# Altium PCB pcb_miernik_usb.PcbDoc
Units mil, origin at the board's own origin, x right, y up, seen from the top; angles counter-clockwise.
Board outline 6000 x 4000 mil, 2 copper layers (Top Layer, Bottom Layer); 39 components, 50 nets, 152 pads, 21 vias.
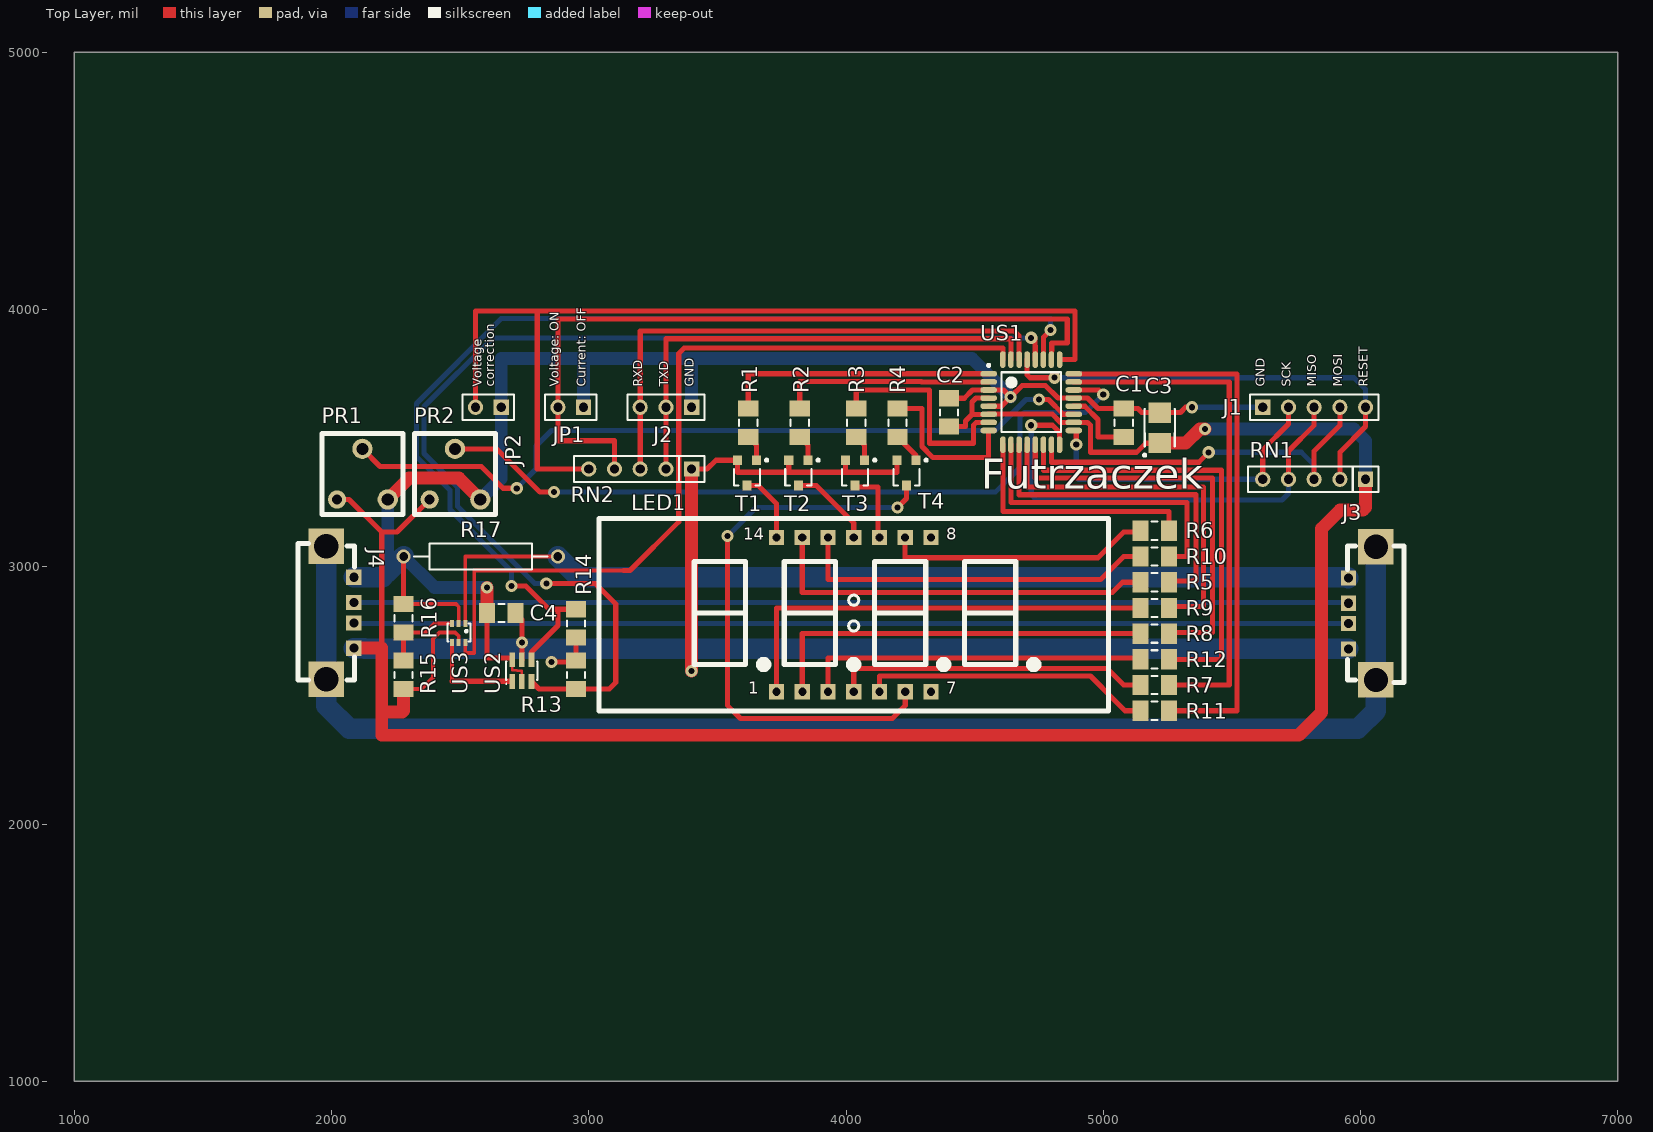
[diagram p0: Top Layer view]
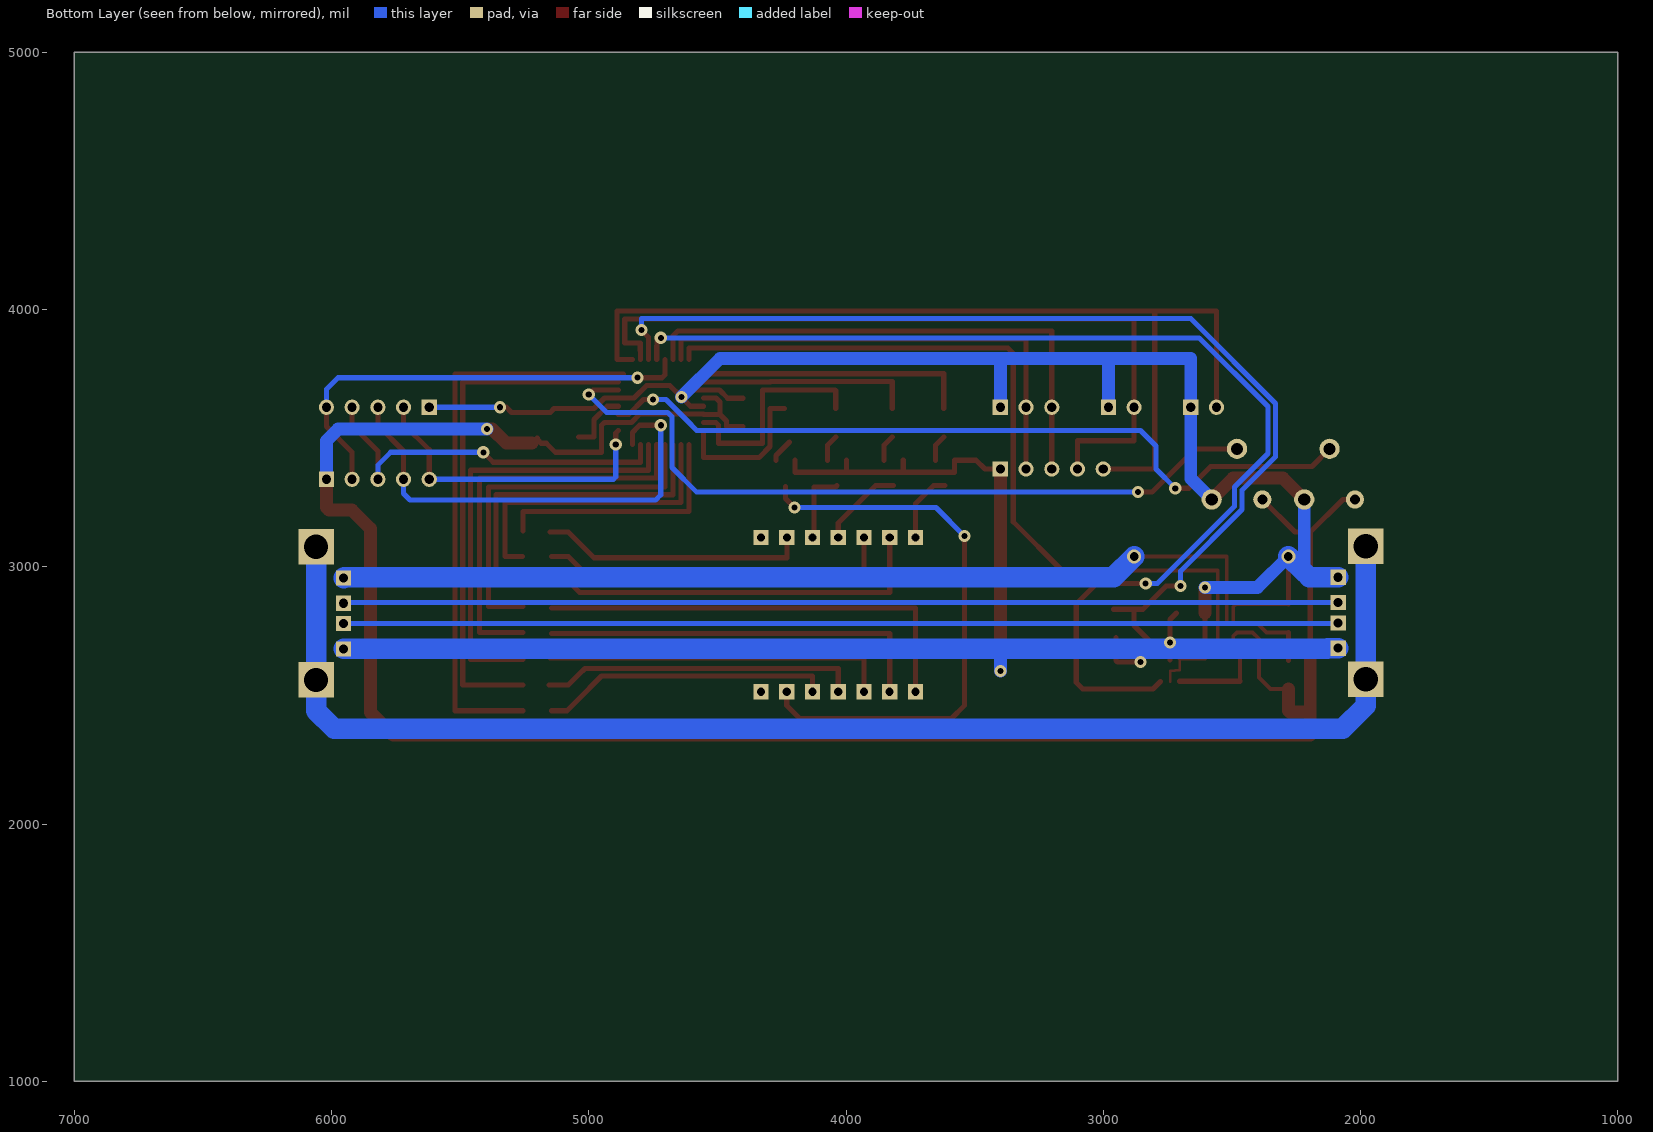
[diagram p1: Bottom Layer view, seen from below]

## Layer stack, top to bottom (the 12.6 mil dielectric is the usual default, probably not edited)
Top Layer: signal copper 1.4
Dielectric: dielectric 12.6, FR-4, Dk 4.8
Bottom Layer: signal copper 1.4

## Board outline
1000,1000 7000,1000 7000,5000 1000,5000

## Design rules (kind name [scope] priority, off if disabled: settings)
Clearance [All] p1: gap=10
PolygonConnect [All] p1: connectstyle=Relief reliefconductorwidth=10 reliefentries=4 polygonreliefangle="90 Angle"
RoutingVias [All] p1: holewidth=28 width=50 viastyle="Through Hole" minholewidth=28 minwidth=50 maxholewidth=28 maxwidth=50
SilkscreenOverComponentPads [All] p1: minsilkscreentomaskgap=10
SolderMaskExpansion [All] p1: expansion=4
Width [All] p1: maxlimit=100 minlimit=10 preferedwidth=50
27 further rules are at their usual default settings.

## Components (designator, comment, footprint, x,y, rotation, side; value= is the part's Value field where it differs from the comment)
C1 "100n" MELF-1206 5080,3560 r270 top
C2 "100n" MELF-1206 4400,3600 r270 top
C3 "22u/16V B" "Tantal B 3528-1411" 5220,3540 r90 top
C4 "100n" MELF-1206 2660,2820 r0 top
J1 "Header 5" HDR1X5 5620,3620 r0 top
J2 "Header 3" HDR1X3 3400,3620 r180 top
J3 "USB connector female" "USB A ¿eñski" 6060,2560 r90 top
J4 "USB connector male" "USB A mêski" 1980,3080 r270 top
JP1 "Header 2" HDR1X2 2980,3620 r180 top
JP2 "Header 2" HDR1X2 2660,3620 r180 top
LED1 "AF5643" "Wyœw LED-AF5643" 3040,2440 r0 top
PR1 "10k" "pot mont poziom" 2120,3360 r0 top
PR2 "10k" "pot mont poziom" 2480,3360 r0 top
R1 "4,7k" MELF-1206 3620,3560 r270 top
R2 "4,7k" MELF-1206 3820,3560 r270 top
R3 "4,7k" MELF-1206 4040,3560 r270 top
R4 "4,7k" MELF-1206 4200,3560 r270 top
R5 "100" MELF-1206 5200,2940 r180 top
R6 "100" MELF-1206 5200,3140 r180 top
R7 "100" MELF-1206 5200,2540 r180 top
R8 "100" MELF-1206 5200,2740 r180 top
R9 "100" MELF-1206 5200,2840 r180 top
R10 "100" MELF-1206 5200,3040 r180 top
R11 "100" MELF-1206 5200,2440 r180 top
R12 "100" MELF-1206 5200,2640 r180 top
R13 "4,7k" MELF-1206 2950,2580 r90 top
R14 "4,7k" MELF-1206 2950,2780 r270 top
R15 "56k" MELF-1206 2280,2580 r270 top
R16 "33k" MELF-1206 2280,2800 r270 top
R17 "0,1 1W" "rez 15mm" 2580,3040 r0 top
RN1 "4x10k" SIL5 6020,3340 r180 top
RN2 "4x10k" SIL5 3400,3380 r180 top
T1 "BC857" 318-08 3615,3365 r180 top
T2 "BC857" 318-08 3815,3365 r180 top
T3 "BC857" 318-08 4035,3365 r180 top
T4 "BC857" 318-08 4235,3365 r180 top
US1 "ATmega8" 32A_N 4720,3640 r0 top
US2 "MCP3425" SOT-23-6 2740,2596.22 r0 top
US3 "NC7SB3157" SC70 2520,2780 r180 top

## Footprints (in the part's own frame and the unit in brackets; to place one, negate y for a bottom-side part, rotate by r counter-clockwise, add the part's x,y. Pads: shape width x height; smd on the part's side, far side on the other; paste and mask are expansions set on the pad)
32A_N [mm] "Thin QFP, 32-Leads, Body 7x7mm, Pitch 0.8mm, IPC Medium Density"
  oval 1.65x0.55 smd: 1(-4.2,2.8) 2(-4.2,2) 3(-4.2,1.2) 4(-4.2,0.4) 5(-4.2,-0.4) 6(-4.2,-1.2) 7(-4.2,-2) 8(-4.2,-2.8) 17(4.2,-2.8) 18(4.2,-2) 19(4.2,-1.2) 20(4.2,-0.4) 21(4.2,0.4) 22(4.2,1.2) 23(4.2,2) 24(4.2,2.8)
  oval 0.55x1.65 smd: 9(-2.8,-4.2) 10(-2,-4.2) 11(-1.2,-4.2) 12(-0.4,-4.2) 13(0.4,-4.2) 14(1.2,-4.2) 15(2,-4.2) 16(2.8,-4.2) 25(2.8,4.2) 26(2,4.2) 27(1.2,4.2) 28(0.4,4.2) 29(-0.4,4.2) 30(-1.2,4.2) 31(-2,4.2) 32(-2.8,4.2)
  silkscreen extent -4.32,-2.95 2.95,3.75, body extent -3.5,-3.5 3.5,3.5, height 1.2
318-08 [mm] "SOT-23; 3 Leads; Body 3.0 x 2.6 mm, inc. leads (LxW max)"
  rect 0.9x0.95 smd: 1(-0.95,-1.25) 2(0.95,-1.25) 3(0,1.25)
  silkscreen extent -2.08,-1.37 1.3,1.25
HDR1X2 [mm] "Connector; Header; 2 Position"
  rect 1.5x1.5 hole 0.9: 1(0,0)
  round 1.5 hole 0.9: 2(2.54,0)
  silkscreen extent -1.27,-1.27 3.81,1.27
HDR1X3 [mm] "Connector; Header; 3 Position"
  rect 1.5x1.5 hole 0.9: 1(0,0)
  round 1.5 hole 0.9: 2(2.54,0) 3(5.08,0)
  silkscreen extent -1.27,-1.27 6.35,1.27
HDR1X5 [mm] "Connector; Header; 5 Position"
  rect 1.5x1.5 hole 0.9: 1(0,0)
  round 1.5 hole 0.9: 2(2.54,0) 3(5.08,0) 4(7.62,0) 5(10.16,0)
  silkscreen extent -1.27,-1.27 11.43,1.27
MELF-1206 [mm] "Metal Electrode Face (MELF) Resistor; Body 3.2 x 1.8 mm (LxDia)"
  rect 1.6x2 smd: 1(-1.4,0) 2(1.4,0)
  silkscreen extent -0.3,-0.9 0.3,0.9, body extent -2.3,-1.1 2.3,1.1, height 1.85
"pot mont poziom" [mm]
  round 1.8 hole 1: a(-2.5,-2.5)
  round 2 hole 1.2: b(2.5,-2.5) c(0,2.5)
  silkscreen extent -4,-4 4,4
"rez 15mm" [mm]
  round 1.4 hole 0.85: 1(-7.62,0) 2(7.62,0)
  silkscreen extent -6.6,-1.27 6.6,1.27, body extent -5.08,-1.27 5.08,1.27, height 2.54
SC70 [mm]
  rect 0.4x0.7 smd: 1(0,0) 2(0.65,0) 3(1.3,0) 4(1.3,1.9) 5(0.65,1.9) 6(0,1.9)
  silkscreen extent -0.51,0 1.78,1.78, body extent -0.51,0 1.78,1.78, height 1
SIL5 [mm] "Connector; Header; 9 Position"
  rect 1.5x1.5 hole 0.9: 1(0,0)
  round 1.5 hole 0.9: 2(2.54,0) 3(5.08,0) 4(7.62,0) 5(10.16,0)
  silkscreen extent -1.27,-1.27 11.6,1.27
SOT-23-6 [mm]
  rect 0.55x1.45 smd: 1(-0.95,-1.075) 2(0,-1.075) 3(0.95,-1.075) 4(0.95,1.075) 5(0,1.075) 6(-0.95,1.075)
  silkscreen extent -1.57,-1.35 1.55,0.9, body extent -1.52,-1.02 1.52,1.02, height 1.45
"Tantal B 3528-1411" [mm] "Capacitor, SM Tantalum; Body 3.5 x 2.8 mm (LxW typ)"
  rect 2x2.2 smd: 1(-1.5,0) 2(1.5,0)
  silkscreen extent -2.82,-1.5 1.85,1.62, body extent -2.6,-1.2 2.6,1.2, height 2.5
"USB A mêski" [mm] "z³¹cze USB typu A na krawêdzi p³ytki"
  rect 1.5x1.5 hole 0.9: 1(10.07,2.71) 2(7.57,2.71) 3(5.57,2.71) 4(3.07,2.71)
  rect 3.5x3.5 hole 2.4: 5(0,0) 5(13.14,0)
  silkscreen extent -0.25,-2.79 13.21,2.79
"USB A ¿eñski" [mm] "z³¹cze USB typu A na krawêdzi p³ytki"
  rect 1.5x1.5 hole 0.9: 1(3.07,2.71) 2(5.57,2.71) 3(7.57,2.71) 4(10.07,2.71)
  rect 3.5x3.5 hole 2.4: 5(0,0) 5(13.14,0)
  silkscreen extent -0.25,-2.79 13.21,2.79
"Wyœw LED-AF5643" [mm]
  rect 1.5x1.5 hole 0.8: 1(17.53,1.88) 2(20.07,1.88) 3(22.61,1.88) 4(25.15,1.88) 5(27.69,1.88) 6(30.23,1.88) 7(32.77,1.88) 8(32.766,17.12) 9(30.226,17.12) 10(27.686,17.12) 11(25.146,17.12) 12(22.606,17.12) 13(20.066,17.12) 14(17.526,17.12)
  silkscreen extent 0,0 50.3,19, body extent 0,0 50.3,19, height 8

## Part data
C1 C2 C4: library part kondensator
C3: library part "kond biegunowy", "Polarized Capacitor"
J1: "Header, 5-Pin"
J2: "Header, 3-Pin"
J3 J4: library part "USB connector"
JP1 JP2: "Header, 2-Pin"
LED1: library part "wyœwietlacz LED-AF5643"
PR1 PR2: library part "pot mont"
R1 R2 R3 R4 R5 R6 R7 R8 R9 R10 R11 R12 R13 R14 R15 R16 R17: library part rezystor
RN1 RN2: library part "drab rez x 4", "drab rez x 4"
T1 T2 T3 T4: library part BC857ALT1, "General Purpose Transistor PNP Silicon"
US1: library part ATmega8-16AC, "8-Bit AVR Microcontroller with 8K Bytes of In-System Programmable Flash Memory"
US2: "A/D 16-bit I2C"

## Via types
v1: diameter 47.24, hole 23.62, Top Layer to Bottom Layer, 21 vias

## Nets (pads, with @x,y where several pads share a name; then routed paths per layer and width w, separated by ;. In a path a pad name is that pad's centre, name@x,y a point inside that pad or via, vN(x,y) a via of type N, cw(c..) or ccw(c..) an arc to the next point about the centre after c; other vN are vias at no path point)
+5V: C2.2 C3.1 C4.2 J3.1 J4.1 PR1.a PR2.a R13.2 R14.2 R15.2 RN1.1 RN2.1 T1.2 T2.2 T3.2 T4.2 US1.4 US1.6 US1.18 US2.5 US3.5 | length 15120.2
  Top Layer w15: R15.2 2349.88,2524.88 2395,2570 2395,2720 2420,2745 2480,2745 2494.41,2730.59 US3.5
  Top Layer w20: PR1.a 2068.43,3261.57 2195,3135 ; 2195,2524.88 2195,2683.54 2195,3135 ; PR2.a 2255,3135 2195,3135 ; C4.2 2740,2795.12 v1(2740,2705) US2.5 ; v1(2855,2630) 2944.88,2630 R13.2 R14.2 ; RN2.1 3460,3380 3494.21,3414.21 T1.2 3577.6,3367.4 4197.6,3367.4 T4.2 ; 3777.6,3369.8 T2.2 ; 3997.6,3369.8 T3.2 ; C2.2 4464.88,3544.88 4465,3545 4465,3567.01 4490,3592.01 ; US1.6@4553.98,3592.09 4520.22,3592.09 4520.14,3592.01 4490,3592.01 ; US1.6 4555.31,3593.43 4640.85,3593.43 4701.73,3593.43 4701.93,3593.62 4738.07,3593.62 4738.27,3593.43 4801.57,3593.43 4833.74,3561.26 US1.18 4938.74,3561.26 4950,3550 4950,3445 5130,3445 5165,3480 5185,3480 5195.94,3490.94 5210,3490.94 C3.1@5200,3500.94 ; US1.4 4505.75,3655.75 4490,3640 4490,3592.01
  Top Layer w50: J4.1 2195,2683.54 2195,2435 ; R15.2 2280,2440 2275,2435 2195,2435 ; v1(3400,2595) RN2.1 ; C3.1 5320.94,3480.94 5375,3535 v1(5395,3535) ; RN1.1 6020,3230 6010,3220 5920,3220 5849.13,3149.13 5849.13,2434.13 5760,2345 2195,2345 2195,2435
  Bottom Layer w20: 2740,2680.87 v1(2740,2705) ; v1(2855,2630) 2855,2675.87
  Bottom Layer w50: v1(3400,2595) 3400,2675.87 ; v1(5395,3535) 5975,3535 6020,3490 RN1.1
  Bottom Layer w80: J4.1 2126.69,2683.54 ; 2129.37,2680.87 2740,2680.87 J3.1
A: R5.1 US1.11 | length 1325.9
  Top Layer w20: US1.11 4672.76,3280 5360,3280 5360,2945 5265.12,2945 R5.1@5255.12,2935
A1: R1.1 US1.1 | length 1069.8
  Top Layer w20: R1.1 3620,3750.24 US1.1
A2: R2.1 US1.2 | length 840
  Top Layer w20: R2.1 3820,3720 4292.43,3720 4293.69,3718.74 US1.2
A3: R3.1 US1.7 | length 867.7
  Top Layer w20: R3.1 4040,3685 4042.48,3687.48 4325,3687.48 4325,3480 4495,3480 4495,3550 4506.26,3561.26 US1.7
A4: R4.1 US1.8 | length 584.6
  Top Layer w20: 4240,3615.12 4295,3615.12 4295,3467.57 4337.57,3425 4554.65,3425 US1.8
B: R6.1 US1.9 | length 980
  Top Layer w20: US1.9 4609.76,3215 5255.12,3215 R6.1
C: R7.1 US1.23 | length 2018.3
  Top Layer w20: US1.23 5490,3718.74 5490,2540 R7.1
D: R8.1 US1.13 | length 1588.8
  Top Layer w20: US1.13 4735.75,3345 5425,3345 5425,2745 R8.1@5255.12,2745
DP: R12.1 US1.14 | length 1732.3
  Top Layer w20: US1.14 4767.24,3375 5460,3375 5460,2640 R12.1
E: R9.1 US1.12 | length 1450.3
  Top Layer w20: US1.12 4704.25,3310 5390,3310 5390,2845 R9.1@5255.12,2845
F: R10.1 US1.10 | length 1186
  Top Layer w20: US1.10 4641.26,3250 5325,3250 5325,3040 R10.1@5257.36,3040
G: R11.1 US1.24 | length 2229.5
  Top Layer w20: US1.24@4865.35,3750 5520,3750 5520,2440 R11.1
GND: C1.1 C2.1 C3.2 C4.1 J1.1 J2.1 J4.4 JP1.1 JP2.1 PR1.b PR2.b R16.1 R17.1 US1.3 US1.5 US1.21 US2.2 US2.6 US3.2 | length 6669.5
  Top Layer w10: US2.6 2702.6,2597.44 2719.64,2597.44 2722.08,2595 2740,2595 US2.2
  Top Layer w15: R16.1 2483.7,2855.12 2494.41,2844.41 US3.2
  Top Layer w20: R16.1 R17.1 ; C4.1 2604.88,2730.12 2604.88,2645 US2.6@2702.6,2645 ; C2.1 4400.12,3655 4460,3655 4492.24,3687.24 US1.3 4612.76,3687.24 v1(4640,3660) ; US1.5 4604.25,3624.25 v1(4640,3660) ; v1(5345,3620) 5320,3620 5300,3600 5150,3600 5135,3615 4980,3615 4939.25,3655.75 US1.21 4824.25,3655.75 4775,3705 4685,3705 v1(4640,3660)
  Top Layer w50: PR1.b 2301.85,3345 2495,3345 PR2.b ; C4.1@2605,2820.12 v1(2605,2920)
  Bottom Layer w20: v1(5345,3620) J1.1
  Bottom Layer w50: 2218.43,2978.43 PR1.b ; R17.1 2400,2920 v1(2605,2920) ; PR2.b 2660,3343.15 JP2.1 2660,3810 2980,3810 ; JP1.1 2980,3810 ; J2.1 3400,3805 3395,3810 ; v1(4640,3660) 4490,3810 3395,3810 ; 2980,3810 3395,3810
  Bottom Layer w80: J4.4 2199.13,2959.13 ; 2218.43,2978.43 R17.1
JP1: JP1.2 RN2.4 US1.26 | length 3002.6
  Top Layer w20: RN2.4 3100,3490 2880,3490 JP1.2 2880,3963.74 4860,3963.74 4860,3870 4800,3870 4800,3840.37 4799.41,3839.78 4799.41,3806.02 US1.26
JP2: JP2.2 RN2.5 US1.25 | length 3765.6
  Top Layer w20: JP2.2 2560,3993.74 2800,3993.74 ; RN2.5 2800,3380 2800,3993.74 ; US1.25 4890,3805.35 4890,3993.74 2800,3993.74
MISO: J1.3 RN1.4 US1.16 | length 1834.4
  Top Layer w20: v1(4720,3550) 4802.57,3550 4807.57,3545 4830.24,3522.34 US1.16 ; RN1.4 5720,3450 5820,3550 J1.3
  Bottom Layer w20: v1(4720,3550) 4720,3280 4740,3260 5695,3260 5720,3285 RN1.4
MOSI: J1.4 RN1.3 US1.15 | length 1502.8
  Top Layer w20: US1.15 4798.74,3406.26 5371.26,3406.26 v1(5410,3445) ; RN1.3 5820,3450 5920,3550 J1.4
  Bottom Layer w20: v1(5410,3445) 5770,3445 5820,3395 RN1.3
NetC1_2: C1.2 US1.20 | length 243.5
  Top Layer w20: US1.20 4928.32,3624.25 4980,3572.57 4980,3505 5039.88,3505
NetJ3_2: J3.2 J4.2 | length 3863.9
  Bottom Layer w20: J4.2@2089.37,2779.29 J3.2
NetJ3_3: J3.3 J4.3 | length 3863.9
  Bottom Layer w20: J4.3 J3.3@5950.63,2860.71
NetJ3_4: J3.4 R17.2 US3.1 | length 3727.9
  Top Layer w15: US3.1 2520,3040 R17.2
  Bottom Layer w80: R17.2 2960,2960 5949.76,2960 J3.4
NetJ3_5: J3.5 J4.5 | length 5403.6
  Bottom Layer w80: J4.5@1980,3080 1980,2562.68 1980,2460 2070,2370 5990,2370 6060,2440 6060,2560 J3.5@6060,3077.32
NetLED1_1: LED1.1 R9.2 | length 1740.7
  Top Layer w20: LED1.1 3730.16,2840 5000,2840 5090,2840 R9.2
NetLED1_2: LED1.2 R8.2 | length 1540.7
  Top Layer w20: LED1.2 3830.16,2740 5080,2740 R8.2
NetLED1_3: LED1.3 R12.2 | length 1350.8
  Top Layer w20: LED1.3 3930.16,2645 5060,2645 R12.2@5150,2645
NetLED1_4: LED1.4 R7.2 | length 1242.8
  Top Layer w20: LED1.4 4030.16,2605 5015,2605 5040,2580 5080,2540 R7.2@5155,2540
NetLED1_5: LED1.5 R11.2 | length 1131.6
  Top Layer w20: LED1.5 4130.16,2575 4950,2575 5045,2480 5085,2440 R11.2
NetLED1_6: LED1.6 T4.3 | length 2246.4
  Top Layer w20: v1(3540,3120) 3540,2460 3590,2410 4180,2410 4230.16,2460.16 LED1.6 ; v1(4200,3230) 4235,3265 T4.3@4235,3310.79
  Bottom Layer w20: v1(3540,3120) 3650,3230 v1(4200,3230)
NetLED1_9: LED1.9 R6.2 | length 1040.4
  Top Layer w20: LED1.9 4230,3035 4980,3035 5080,3135 R6.2@5150,3135
NetLED1_10: LED1.10 T3.3 | length 283.4
  Top Layer w20: T3.3 4040.79,3310 4125,3310 LED1.10@4125,3119.02
NetLED1_11: LED1.11 T2.3 | length 331.4
  Top Layer w20: T2.3 3884.21,3315.79 4030,3170 LED1.11
NetLED1_12: LED1.12 R10.2 | length 1416.2
  Top Layer w20: LED1.12 3930,2950 4990,2950 5080,3040 R10.2
NetLED1_13: LED1.13 R5.2 | length 1545.5
  Top Layer w20: LED1.13 3830,2900 5000,2900 5035,2900 5075,2940 R5.2
NetLED1_14: LED1.14 T1.3 | length 275.3
  Top Layer w20: T1.3 3659.21,3315.79 3730,3245 LED1.14
NetR1_2: R1.2 T1.1 | length 104.1
  Top Layer w20: R1.2 3652.4,3472.48 T1.1
NetR2_2: R2.2 T2.1 | length 104.1
  Top Layer w20: R2.2 3852.4,3472.48 T2.1
NetR3_2: R3.2 T3.1 | length 104.1
  Top Layer w20: R3.2 4072.4,3472.48 T3.1
NetR4_2: R4.2 T4.1 | length 92.4
  Top Layer w20: R4.2@4220,3484.88 4272.4,3432.48 T4.1
NetR15_1: R15.1 R16.2 US3.3 | length 313.1
  Top Layer w15: R16.2 2364.88,2744.88 2400,2780 US3.3
  Top Layer w20: R15.1 R16.2
NetUS2_1: US2.1 US3.4 | length 384
  Top Layer w15: 2468.82,2555 US3.4
  Top Layer w20: 2468.82,2555 US2.1@2702.6,2555
PR1: PR1.c US1.19 | length 3048.2
  Top Layer w20: PR1.c 2188.43,3390 2298.43,3390 2581.85,3390 2666.85,3305 v1(2720,3305) ; v1(4750,3650) 4787.43,3650 4844.67,3592.76 US1.19
  Bottom Layer w20: v1(2720,3305) 2795,3380 2795,3470 2855,3530 4580,3530 4620,3570 4700,3650 v1(4750,3650)
PR2: PR2.c US1.22 | length 2984.2
  Top Layer w20: PR2.c 2641.57,3458.43 2810,3290 v1(2865,3290) ; US1.22 4982.76,3687.24 v1(5000,3670)
  Bottom Layer w20: v1(2865,3290) 4295,3290 4580,3290 4676.38,3386.38 4676.38,3583.07 4693.31,3600 4930,3600 v1(5000,3670)
RESET: J1.5 RN1.2 US1.29 | length 1789.9
  Top Layer w20: US1.29 4704.25,3745.75 4715,3735 v1(4810,3735) ; RN1.2 5920,3445 6020,3545 J1.5
  Bottom Layer w20: v1(4810,3735) 5975,3735 6020,3690 J1.5
RXD: J2.3 RN2.3 US1.30 | length 2108.8
  Top Layer w20: RN2.3 J2.3 3200,3916.26 4653.69,3916.26 4672.09,3897.86 4672.09,3806.02 US1.30
S: US1.32 US3.6 | length 3235.6
  Top Layer w15: US3.6 2520,2665.18 2555,2665.18 2555,2985 3135,2985
  Top Layer w20: 3135,2985 3160,2985 3350,3175 3350,3829.53 3370.24,3849.76 4609.76,3849.76 US1.32
SCK: J1.2 RN1.5 US1.17 | length 1234.3
  Top Layer w20: US1.17 4895,3520.12 v1(4895,3475) ; RN1.5 5620,3455 5720,3555 J1.2
  Bottom Layer w20: v1(4895,3475) 4895,3350 4905,3340 RN1.5
SCL: R13.1 US1.28 US2.3 | length 4439.1
  Top Layer w20: US2.3 2806.42,2524.88 R13.1 3079.88,2524.88 3105,2550 3105,2855 3025,2935 v1(2835,2935) ; v1(4720,3890) 4734.25,3890 4734.25,3858.5 4735.75,3857.01 US1.28
  Bottom Layer w20: v1(2835,2935) 2790,2935 2490,3235 2490,3310 2360,3440 2360,3622.57 2627.43,3890 v1(4720,3890)
SDA: R14.1 US1.27 US2.4 | length 4142.4
  Top Layer w20: v1(2700,2925) 2755,2925 2777.4,2902.6 2844.88,2835.12 2880,2835.12 ; 2777.4,2668.54 2880,2771.14 2880,2835.12 ; R14.1@2960,2835.12 R14.1 2880,2835.12 ; US1.27 4767.24,3892.24 v1(4795,3920)
  Bottom Layer w20: v1(2700,2925) 2700,2982.57 2460,3222.57 2460,3297.57 2330,3427.57 2330,3635 2660,3965 4795,3965 v1(4795,3920)
TXD: J2.2 RN2.2 US1.31 | length 1928.4
  Top Layer w20: RN2.2 J2.2 3300,3886.26 4641.26,3886.26 US1.31
pads on no net: LED1.7 LED1.8

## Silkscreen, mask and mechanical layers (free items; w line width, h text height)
Top Overlay:
  text "Voltage" at 2595,3700 h60 r90
  text "correction" at 2645,3700 h60 r90
  text "Voltage: ON" at 2895,3700 h60 r90
  text "Current: OFF" at 3000,3700 h60 r90
  text "RXD" at 3220,3700 h60 r90
  text "TXD" at 3320,3700 h60 r90
  text "GND" at 3420,3700 h60 r90
  text "GND" at 5640,3700 h60 r90
  text "SCK" at 5740,3700 h60 r90
  text "MISO" at 5840,3700 h60 r90
  text "MOSI" at 5940,3700 h60 r90
  text "RESET" at 6040,3700 h60 r90
  text "Futrzaczek" at 4525,3265 h200
Mechanical 1:
  lines w10: 1860,2285 6200,2285 6200,4050 2980,4050 1860,4050 1860,2285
